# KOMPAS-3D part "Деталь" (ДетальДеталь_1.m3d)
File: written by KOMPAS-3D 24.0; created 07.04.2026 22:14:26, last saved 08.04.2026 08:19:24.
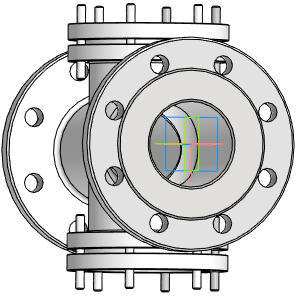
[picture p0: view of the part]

Document properties: Автор: Main; Полное имя файла: D:\DN.ru Аутсерс\Стекло смотровое DN.ru\Исходники\Стекло смотровое DN.ru SG2-34G-F тип В ГОСТ 21836-2021 Ду80 Ру16, углеродистая сталь, фланцевое\ДетальДеталь_1.m3d

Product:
- Body: Твердое тело1  | qty 1
    Масса: 18.583108
- Part/product: Деталь
    Масса: 18.583108
    additional columns: Типовые

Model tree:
1. Твердое тело1  (labels: Твердое тело1)
2. Эскиз:1  (labels: Грань.Твердое тело1)
3. Элемент выдавливания:1  (labels: Грань.Твердое тело1)
     Расстояние 2 = 20
4. Эскиз:2  (labels: Грань.Твердое тело1)
5. Элемент выдавливания:2  (labels: Грань.Твердое тело1)
     Расстояние 2 = 20
6. Эскиз:3  (with: Грань.Элемент выдавливания:2)
7. Элемент выдавливания:3  (labels: Грань.Твердое тело1)
     Расстояние 2 = 20
8. Эскиз:4  (with: Грань.Элемент выдавливания:1)
9. Элемент выдавливания:4  (labels: Грань.Твердое тело1)
     Расстояние 2 = 20

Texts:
  Шаг 1
  Шаг 2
